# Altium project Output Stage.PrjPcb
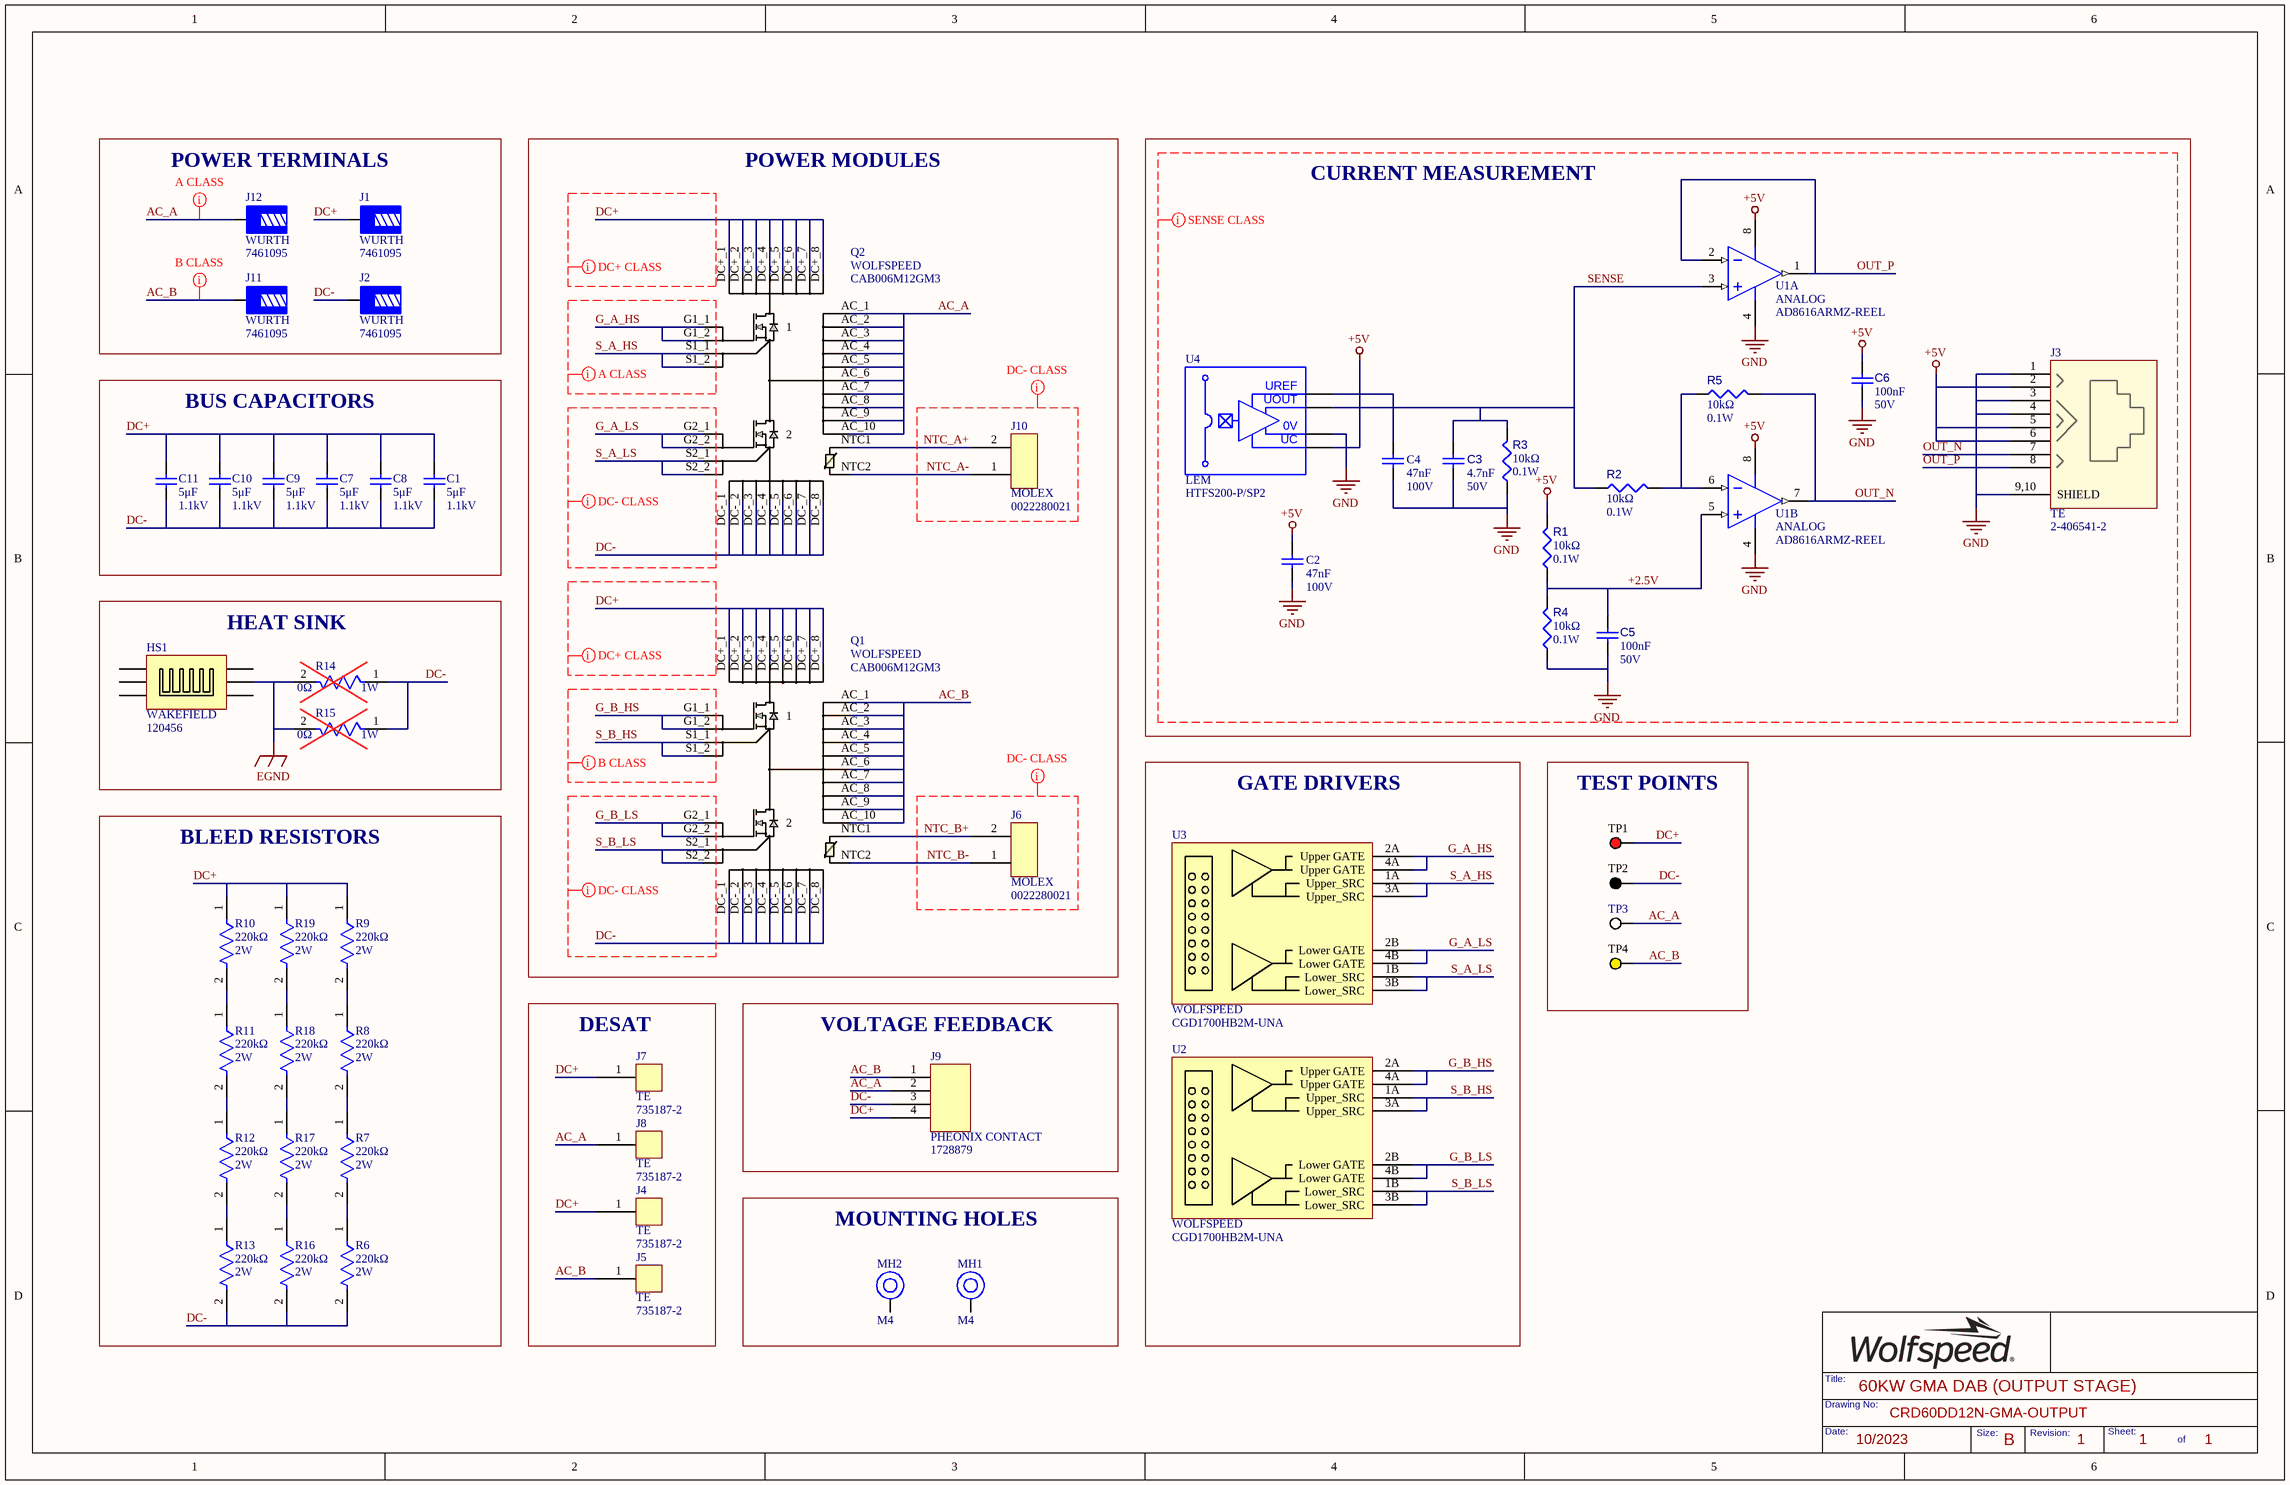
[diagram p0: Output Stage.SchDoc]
1 sheet, 55 parts. Net scope: global (net labels, ports and power ports of the same name join across sheets).
Board file: Output Stage.PcbDoc

## Sheet Output Stage.SchDoc: 60KW GMA DAB (OUTPUT STAGE)
size 431 x 279 mm; Date: 10/2023; DocumentNumber: CRD60DD12N-GMA-OUTPUT; Revision: 1; SheetNumber: 1; SheetTotal: 1; SheetSize: B

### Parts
C1  Capacitance: 5μF  Voltage Rating (DC): 1.1kV  [C4AQQBU4500A11J]  (hidden comment: C4AQQBU4500A11J)
C2  value 47nF  Voltage Rating: 100V  [FP-C0603C-CF-IPC_B]  (hidden comment: CGA3E3X7S2A473K080AB)
C3  value 4.7nF  Voltage Rating: 50V  [FP-C0603C-CF-IPC_B]  (hidden comment: C0603C472K5RACAUTO)
C4  value 47nF  Voltage Rating: 100V  [FP-C0603C-CF-IPC_B]  (hidden comment: CGA3E3X7S2A473K080AB)
C5  value 100nF  Voltage Rating: 50V  [FP-C0603C-CF-IPC_B]  (hidden comment: CL10B104KB8NNWC)
C6  value 100nF  Voltage Rating: 50V  [FP-C0603C-CF-IPC_B]  (hidden comment: CL10B104KB8NNWC)
C7  Capacitance: 5μF  Voltage Rating (DC): 1.1kV  [C4AQQBU4500A11J]  (hidden comment: C4AQQBU4500A11J)
C8  Capacitance: 5μF  Voltage Rating (DC): 1.1kV  [C4AQQBU4500A11J]  (hidden comment: C4AQQBU4500A11J)
C9  Capacitance: 5μF  Voltage Rating (DC): 1.1kV  [C4AQQBU4500A11J]  (hidden comment: C4AQQBU4500A11J)
C10  Capacitance: 5μF  Voltage Rating (DC): 1.1kV  [C4AQQBU4500A11J]  (hidden comment: C4AQQBU4500A11J)
C11  Capacitance: 5μF  Voltage Rating (DC): 1.1kV  [C4AQQBU4500A11J]  (hidden comment: C4AQQBU4500A11J)
HS1  Manufacturer: WAKEFIELD  [120456]  (hidden comment: 120456)
J1  Manufacturer: WURTH  [7461095_chemical surface]  (hidden comment: 7461095)
J2  Manufacturer: WURTH  [7461095_chemical surface]  (hidden comment: 7461095)
J3  Manufacturer: TE  [2-406541-2]  (hidden comment: 2-406541-2)
J4  735187-2  Manufacturer: TE  [735187-2]
J5  735187-2  Manufacturer: TE  [735187-2]
J6  0022280021  Manufacturer: MOLEX  [0022280021]
J7  735187-2  Manufacturer: TE  [735187-2]
J8  735187-2  Manufacturer: TE  [735187-2]
J9  1728879  Manufacturer: PHEONIX CONTACT  [1728879]
J10  0022280021  Manufacturer: MOLEX  [0022280021]
J11  Manufacturer: WURTH  [7461095_chemical surface]  (hidden comment: 7461095)
J12  Manufacturer: WURTH  [7461095_chemical surface]  (hidden comment: 7461095)
MH1  Size: M4  [MH_M4_P]  (hidden comment: MH_M4_P)
MH2  Size: M4  [MH_M4_P]  (hidden comment: MH_M4_P)
Q1  CAB006M12GM3  Manufacturer: WOLFSPEED  [GM3_CRW_MH]
Q2  CAB006M12GM3  Manufacturer: WOLFSPEED  [GM3_CRW_MH]
R1  value 10kΩ  Power: 0.1W  [FP-AC0603-IPC_B]  (hidden comment: RG1608P-103-BT5)
R2  value 10kΩ  Power: 0.1W  [FP-AC0603-IPC_B]  (hidden comment: RG1608P-103-BT5)
R3  value 10kΩ  Power: 0.1W  [FP-AC0603-IPC_B]  (hidden comment: RG1608P-103-BT5)
R4  value 10kΩ  Power: 0.1W  [FP-AC0603-IPC_B]  (hidden comment: RG1608P-103-BT5)
R5  value 10kΩ  Power: 0.1W  [FP-AC0603-IPC_B]  (hidden comment: RG1608P-103-BT5)
R6  value 220kΩ  Power Rating: 2W  [FP-CRGP2512-IPC_C]  (hidden comment: CRGP2512F220K)
R7  value 220kΩ  Power Rating: 2W  [FP-CRGP2512-IPC_C]  (hidden comment: CRGP2512F220K)
R8  value 220kΩ  Power Rating: 2W  [FP-CRGP2512-IPC_C]  (hidden comment: CRGP2512F220K)
R9  value 220kΩ  Power Rating: 2W  [FP-CRGP2512-IPC_C]  (hidden comment: CRGP2512F220K)
R10  value 220kΩ  Power Rating: 2W  [FP-CRGP2512-IPC_C]  (hidden comment: CRGP2512F220K)
R11  value 220kΩ  Power Rating: 2W  [FP-CRGP2512-IPC_C]  (hidden comment: CRGP2512F220K)
R12  value 220kΩ  Power Rating: 2W  [FP-CRGP2512-IPC_C]  (hidden comment: CRGP2512F220K)
R13  value 220kΩ  Power Rating: 2W  [FP-CRGP2512-IPC_C]  (hidden comment: CRGP2512F220K)
R14  Max Power Dissipation: 1W  Resistance: 0Ω  [FP-RC2512-0_65-IPC_C]  (hidden comment: RC2512JK-070RL)
R15  Max Power Dissipation: 1W  Resistance: 0Ω  [FP-RC2512-0_65-IPC_C]  (hidden comment: RC2512JK-070RL)
R16  value 220kΩ  Power Rating: 2W  [FP-CRGP2512-IPC_C]  (hidden comment: CRGP2512F220K)
R17  value 220kΩ  Power Rating: 2W  [FP-CRGP2512-IPC_C]  (hidden comment: CRGP2512F220K)
R18  value 220kΩ  Power Rating: 2W  [FP-CRGP2512-IPC_C]  (hidden comment: CRGP2512F220K)
R19  value 220kΩ  Power Rating: 2W  [FP-CRGP2512-IPC_C]  (hidden comment: CRGP2512F220K)
TP1  5010  [KSTN-5010_V]  (value not drawn)
TP2  5011  [KSTN-5011_V]  (value not drawn)
TP3  5012  [KSTN-5012_V]  (value not drawn)
TP4  5014  [KSTN-5014_V]  (value not drawn)
U1  AD8616ARMZ-REEL  Manufacturer: ANALOG  [ADI-RM-8_M]  (parts A,B of 2)
U2  Manufacturer: WOLFSPEED  Manufacturer Part Number: CGD1700HB2M-UNA  [WolfPack Dual Gate Driver Board Assembly-Footprint-3]  (hidden comment: WolfPack Dual Gate Driver Board Assembly)
U3  Manufacturer: WOLFSPEED  Manufacturer Part Number: CGD1700HB2M-UNA  [WolfPack Dual Gate Driver Board Assembly-Footprint-3]  (hidden comment: WolfPack Dual Gate Driver Board Assembly)
U4  Manufacturer: LEM  [HTFS 200-P (No Hole)]  (hidden comment: HTFS200-P/SP2)

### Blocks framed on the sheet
POWER TERMINALS: J1 J2 J11 J12
POWER MODULES: J6 J10 Q1 Q2
CURRENT MEASUREMENT: C2-C6 J3 R1-R5 U1 U4
BUS CAPACITORS: C1 C7-C11
HEAT SINK: HS1 R14 R15
GATE DRIVERS: U2 U3
TEST POINTS: TP1-TP4
BLEED RESISTORS: R6-R13 R16-R19
DESAT: J4 J5 J7 J8
VOLTAGE FEEDBACK: J9
MOUNTING HOLES: MH1 MH2

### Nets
+5V: C2.1 C6.1 J3.2 J3.5 J3.6 R1.2 U1.8(+V) U4.1(UC)
EGND: HS1.2 R14.2 R15.2
GND: C2.2 C3.2 C4.2 C5.2 C6.2 J3.1 J3.3 J3.4 J3.9,10(SHIELD) R3.1 R4.1 U1.4(-V) U4.2(0V)
+2.5V: C5.1 R1.1 R4.2 U1.5(+IN_B)
AC_A: J8.1 J9.2 J12.1 Q2.AC_1 Q2.AC_2 Q2.AC_3 Q2.AC_4 Q2.AC_5 Q2.AC_6 Q2.AC_7 Q2.AC_8 Q2.AC_9 Q2.AC_10 TP3.1
AC_B: J5.1 J9.1 J11.1 Q1.AC_1 Q1.AC_2 Q1.AC_3 Q1.AC_4 Q1.AC_5 Q1.AC_6 Q1.AC_7 Q1.AC_8 Q1.AC_9 Q1.AC_10 TP4.1
DC+: C1.1 C7.1 C8.1 C9.1 C10.1 C11.1 J1.1 J4.1 J7.1 J9.4 Q1.DC+_1 Q1.DC+_2 Q1.DC+_3 Q1.DC+_4 Q1.DC+_5 Q1.DC+_6 Q1.DC+_7 Q1.DC+_8 Q2.DC+_1 Q2.DC+_2 Q2.DC+_3 Q2.DC+_4 Q2.DC+_5 Q2.DC+_6 Q2.DC+_7 Q2.DC+_8 R9.1 R10.1 R19.1 TP1.1
DC-: C1.2 C7.2 C8.2 C9.2 C10.2 C11.2 J2.1 J9.3 Q1.DC-_1 Q1.DC-_2 Q1.DC-_3 Q1.DC-_4 Q1.DC-_5 Q1.DC-_6 Q1.DC-_7 Q1.DC-_8 Q2.DC-_1 Q2.DC-_2 Q2.DC-_3 Q2.DC-_4 Q2.DC-_5 Q2.DC-_6 Q2.DC-_7 Q2.DC-_8 R6.2 R13.2 R14.1 R15.1 R16.2 TP2.1
G_A_HS: Q2.G1_1 Q2.G1_2 U3.2A(Upper_GATE) U3.4A(Upper_GATE)
G_A_LS: Q2.G2_1 Q2.G2_2 U3.2B(Lower_GATE) U3.4B(Lower_GATE)
G_B_HS: Q1.G1_1 Q1.G1_2 U2.2A(Upper_GATE) U2.4A(Upper_GATE)
G_B_LS: Q1.G2_1 Q1.G2_2 U2.2B(Lower_GATE) U2.4B(Lower_GATE)
NTC_A+: J10.2 Q2.NTC1(T1)
NTC_A-: J10.1 Q2.NTC2(T2)
NTC_B+: J6.2 Q1.NTC1(T1)
NTC_B-: J6.1 Q1.NTC2(T2)
OUT_N: J3.7 R5.2 U1.7(OUT_B)
OUT_P: J3.8 U1.1(OUT_A) U1.2(-IN_A)
S_A_HS: Q2.S1_1 Q2.S1_2 U3.1A(Upper_SRC) U3.3A(Upper_SRC)
S_A_LS: Q2.S2_1 Q2.S2_2 U3.1B(Lower_SRC) U3.3B(Lower_SRC)
S_B_HS: Q1.S1_1 Q1.S1_2 U2.1A(Upper_SRC) U2.3A(Upper_SRC)
S_B_LS: Q1.S2_1 Q1.S2_2 U2.1B(Lower_SRC) U2.3B(Lower_SRC)
SENSE: C3.1 R2.1 R3.2 U1.3(+IN_A) U4.3(UOUT)
NetC4_1: C4.1 U4.4(UREF)
NetR2_2: R2.2 R5.1 U1.6(-IN_B)
NetR6_1: R6.1 R7.2
NetR7_1: R7.1 R8.2
NetR8_1: R8.1 R9.2
NetR10_2: R10.2 R11.1
NetR11_2: R11.2 R12.1
NetR12_2: R12.2 R13.1
NetR16_1: R16.1 R17.2
NetR17_1: R17.1 R18.2
NetR18_1: R18.1 R19.2

Not connected (* = marked no-connect by the designer): HS1 1 3 4 5 6; MH1 1; MH2 1

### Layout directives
net class DC- CLASS: DC-, G_A_LS, G_B_LS, NTC_A+, NTC_A-, NTC_B+, NTC_B-, S_A_LS, S_B_LS
net class A CLASS: AC_A, G_A_HS, S_A_HS
net class B CLASS: AC_B, G_B_HS, S_B_HS
net class DC+ CLASS: DC+
net class SENSE CLASS: +2.5V, +5V, GND, OUT_N, OUT_P, SENSE

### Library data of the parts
C1 C7-C11 = C4AQQBU4500A11J: CAP FILM 5UF 5% 1.1KVDC RADIAL; Manufacturer: KEMET; Dielectric Material: PP; ESR (Equivalent Series Resistance): 9.1mR; Value: 5μF
C2 C4 = CGA3E3X7S2A473K080AB: CAP CER 0.047UF 100V X7S 0603; Manufacturer: TDK; Material: 4241ConductorMaterial; Tolerance: 10%
C3 = CMP-001-00119-9: CAP CER 4700PF 50V X7R 0603; Manufacturer: KEMET; Capacitor Type: Ceramic; Tolerance: 10%
C5 C6 = CMP-00017-3: CAP CER 0.1UF 50V X7R 0603; Manufacturer: SAMSUNG; Tolerance: 10%; Capacitor Type: Ceramic
HS1 = 120456: COLD PLATE HEAT SINK EXPOSED
J1 J2 J11 J12 = CMP-03913-18187404-1: TERM REDCUBE M4 16PIN PCB; Insulation: Non-Insulated; Current Rating: 180A; Number of Contacts: 16
J3 = 2-406541-2: CONN MOD JACK R/A 8P8C SHLD
J4 J5 J7 J8 = 735187-2: CONN QC TAB 0.110 SOLDER
J6 J10 = 0022280021: CONN HEADER VERT 2POS 2.54MM
J9 = 1728879: TERM BLOCK HDR 4POS 90DEG 7.62MM
Q1 Q2 = CAB006M12GM3: SIC 2N-CH 1200V; Type: DEV
R1-R5 = CMP-009-00206-2: RES SMD 10K OHM 0.1% 1/10W 0603; Manufacturer: SUSUMU; Manufacturer Part Number: RG1608P-103-B-T5; Voltage Rating: 75V
R6 R8-R13 R16-R19 = CMP-03211-002966-1: RES 220K OHM 1% 2W 2512; Manufacturer: TE; Temperature Coefficient: ±100ppm/°C; Tolerance: 0.01; Voltage Rating: 500V
R7 = CMP-03211-002966-1: CRGP2512 220KΩ 2W ±100ppm/°C 1% 500V; Manufacturer: TE; Tolerance: 0.01
R14 R15 = CMP-2000-06974-2: RES SMD 0 OHM JUMPER 1W 2512; Manufacturer: YAGEO; Tolerance: 5%; Voltage Rating: 200V; Temperature Coefficient: 200ppm/°C; Value: 0Ω
TP1 = CMP-1672-00002-4: PC TEST POINT MULTIPURPOSE RED; Manufacturer: KEYSTONE
TP2 = CMP-1672-00003-4: PC TEST POINT MULTIPURPOSE BLACK; Manufacturer: KEYSTONE
TP3 = CMP-1672-00004-4: PC TEST POINT MULTIPURPOSE WHITE; Manufacturer: KEYSTONE
TP4 = CMP-1672-00006-4: PC TEST POINT MULTI PURP YELLOW; Manufacturer: KEYSTONE
U1 = CMP-0384-01706-1: IC CMOS 2 CIRCUIT 8MSOP; Generic Part Number: AD8616; V Span Min: 2.7V; Amplifiers Per Package: 2; V Span Max: 6V; Input Bias Current: 200fA; Input Offset Voltage: 23uV; Iq/Amp: 2mA; Small Signal Bandwidth: 24MHz; Slew Rate: 12V/us
U2 U3 = CMP-00030-00001-20: GATE DRIVER BOARD 1700V CAPABLE; Sub-part1: TSM-102-02-S-DV
U4 = HTFS 200-P: SENSOR CURRENT HALL 200A AC/DC; Response Time: 7us; Accuracy: 1%; Operating Supply Voltage: 5V; Min Supply Voltage (DC): 4.75V; Max Supply Voltage (DC): 5.25V; Wire/Cable Diameter: 22mm; Overall Height: 46.3mm; Overall Depth: 17mm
